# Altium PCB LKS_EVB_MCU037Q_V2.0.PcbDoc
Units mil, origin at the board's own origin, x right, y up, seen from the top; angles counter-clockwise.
Board outline 1880 x 1275 mil, 2 copper layers (Top Layer, Bottom Layer); 38 components, 32 nets, 119 pads, 49 vias.
Unrouted connection lines stored in the file: 3.
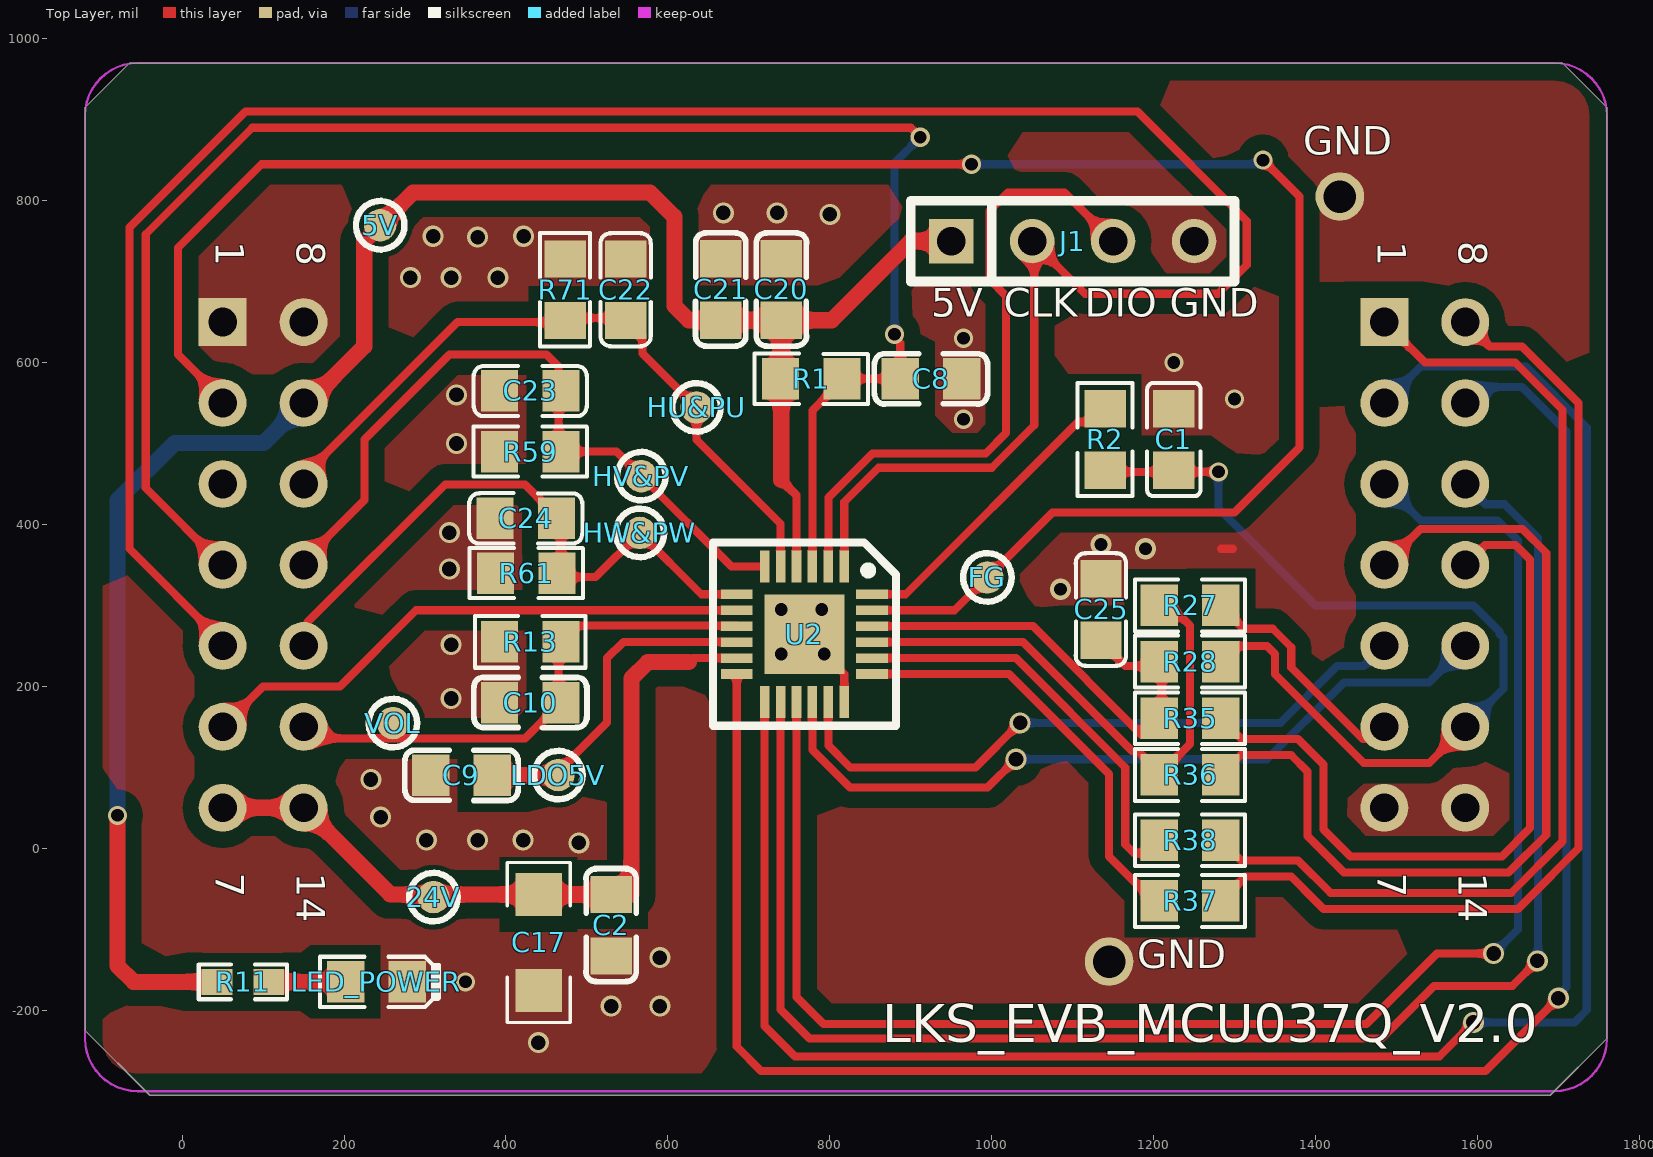
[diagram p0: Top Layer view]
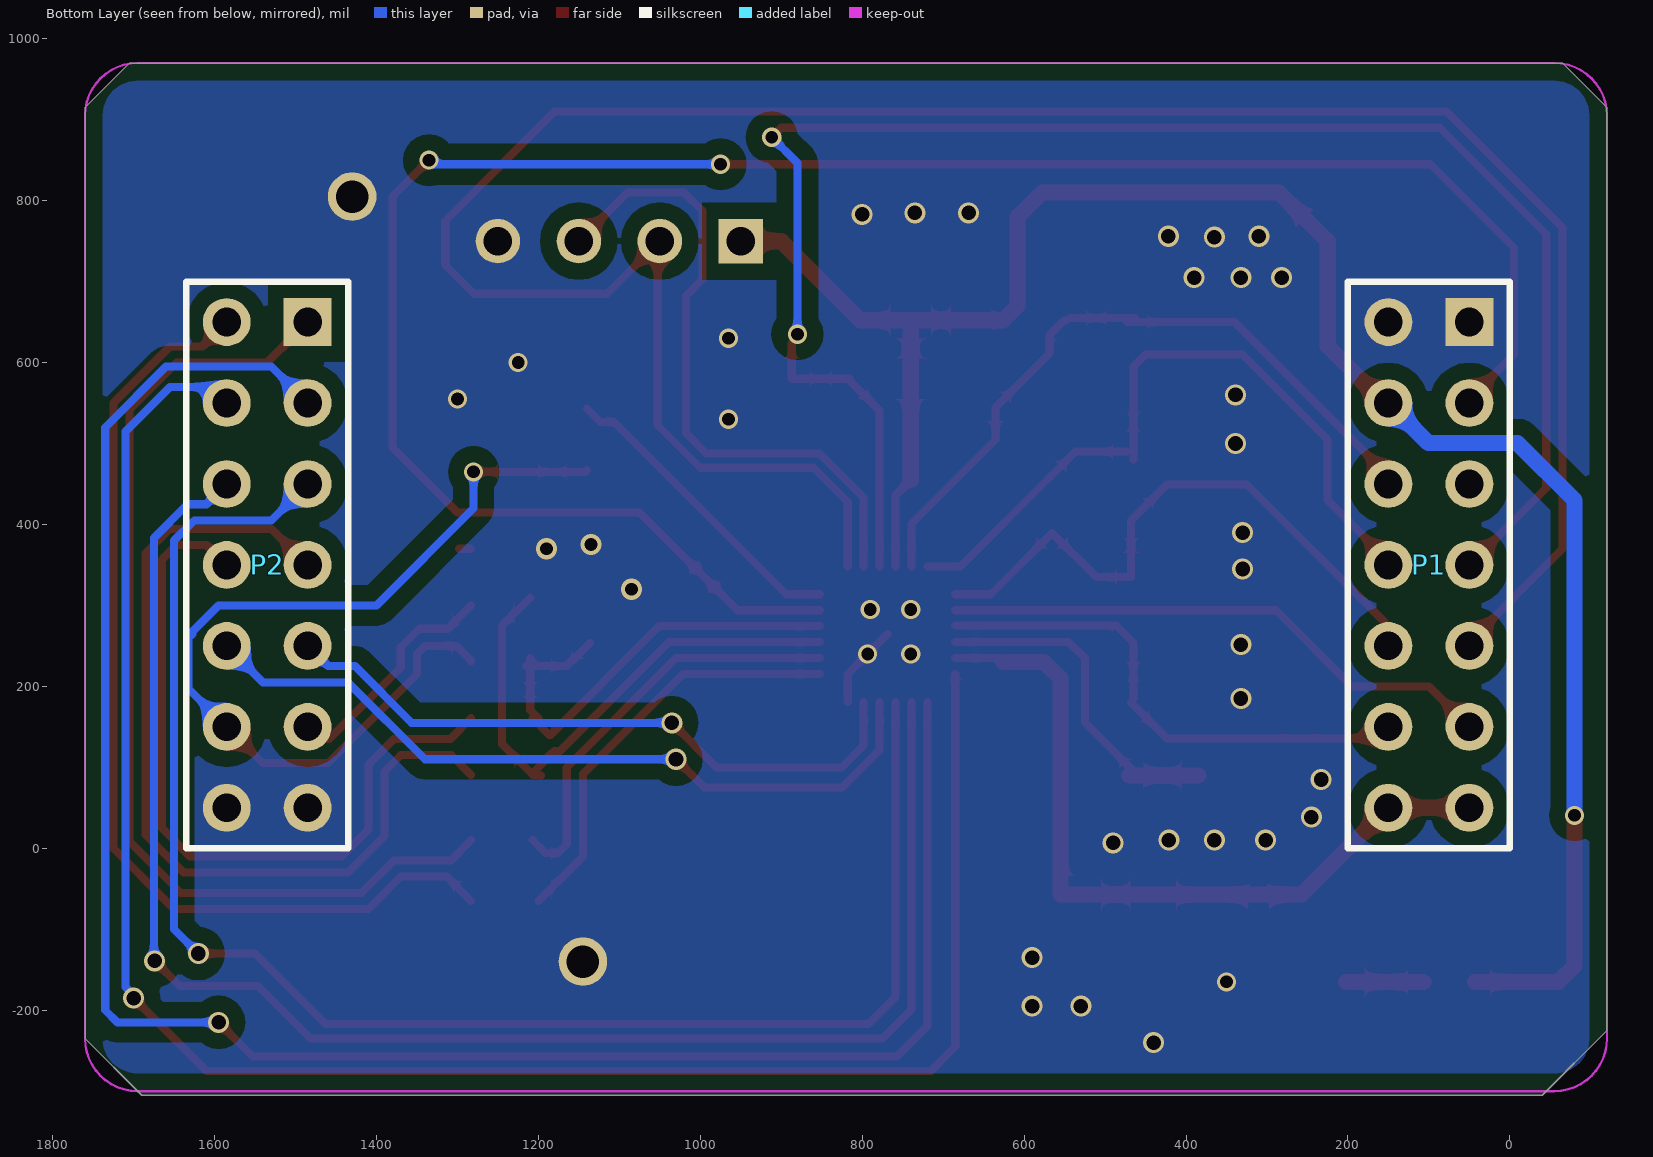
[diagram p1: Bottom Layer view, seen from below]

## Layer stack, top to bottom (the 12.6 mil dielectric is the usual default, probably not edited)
Top Solder: solder mask 0.4, Solder Resist, Dk 3.5
Top Layer: signal copper 1.4
Dielectric1: dielectric 12.6, FR-4, Dk 4.8
Bottom Layer: signal copper 1.4
Bottom Solder: solder mask 0.4, Solder Resist, Dk 3.5

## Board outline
-120,-225 -40,-305 1690,-305 1760,-235 1760,915 1705,970 -65,970 -120,915

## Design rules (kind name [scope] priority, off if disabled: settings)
Clearance Clearance_1 [All vs InPolygon] p1: gap=20 ignorepadtopadclearanceinfootprint=FALSE
Clearance [All] p2: gap=7.87 ignorepadtopadclearanceinfootprint=FALSE
ComponentClearance [All] p1: gap=0 collisioncheckmode=3 verticalgap=0 showdistances=FALSE
FabricationTestpoint [(IsPad And (OnTopLayer Or OnBottomLayer))] p1: side=3 testpointundercomponent=TRUE minsize=40 maxsize=100 preferedsize=60 minholesize=0 maxholesize=40 preferedholesize=32 testpointgrid=1 allowsidetop=TRUE allowsidebottom=TRUE usegrid=TRUE gridtolerance=0.01
PolygonConnect [All] p1: connectstyle=Direct reliefconductorwidth=20 reliefentries=4 polygonreliefangle="90 Angle" airgapwidth=10
RoutingVias [All] p1: holewidth=28 width=50 viastyle="Through Hole" minholewidth=28 minwidth=50 maxholewidth=28 maxwidth=50
SilkToSolderMaskClearance SilkscreenOverComponentPads [IsPad] p1: minsilkscreentomaskgap=10 clearancetoexposedcopper=TRUE
SolderMaskExpansion [All] p1: expansion=4 istentingtop=FALSE
Width [All] p1: maxlimit=300 minlimit=1 preferedwidth=10
27 further rules are at their usual default settings.

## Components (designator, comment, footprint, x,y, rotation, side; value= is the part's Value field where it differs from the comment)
5V "TestP" TP-40 245,770 r0 top
24V "TestP" TP-40 310,-60 r90 top
C1 "1nF/50V" 0805C 1225,505 r270 top
C2 "100nF" 0805C 530,-95 r270 top
C8 "100nF" 0805C 925,580 r0 top
C9 "1uF/10V" 0805C 345,90 r180 top
C10 "100nF" 0805C 430,180 r180 top
C17 "10uF/50V" 1206 440,-175 r90 top
C20 "100nF" 0805C 740.04,690.32 r90 top
C21 "10uF/10V" 0805C 665.04,690.32 r90 top
C22 "1nF/16V" 0805C 548,690 r270 top
C23 "1nF/16V" 0805C 430,565 r0 top
C24 "1nF/16V" 0805C 424.51,407.59 r0 top
C25 "100pF/50V" 0805C 1135,295 r270 top
FG "TestP" TP-40 995,335 r0 top
HU&PU "TestP" TP-40 635,545 r90 top
HV&PV "TestP" TP-40 566.72,460 r90 top
HW&PW "TestP" TP-40 565,390 r90 top
J1 "SWD" SIP4-2.5 1100,750 r0 top
LDO5V "TestP" TP-40 465,90 r270 top
LED_POWER "" 0805D 240,-165 r0 top
P1 "Header 7X2A" HDR2X7_CEN 50,650 r270 bottom
P2 "Header 7X2A" HDR2X7_CEN 1485,650 r270 bottom
R1 "20K" 0805R 777,580 r0 top
R2 "1K" 0805R 1140,505 r90 top
R11 "3.3K" 0603R 75,-165 r180 top
R13 "3.3K" 0805R 430,255 r180 top
R27 "1K" 0805R 1245,300 r0 top
R28 "1K" 0805R 1245,230.59 r0 top
R35 "1K" 0805R 1245,160.59 r180 top
R36 "1K" 0805R 1245,90.59 r180 top
R37 "1K" 0805R 1245,-65 r180 top
R38 "1K" 0805R 1245,10 r180 top
R59 "3.3K" 0805R 430,490 r0 top
R61 "3.3K" 0805R 425,340 r0 top
R71 "3.3K" 0805R 473,690 r270 top
U2 "LKS037Q" QFN24 768.66,264.53 r270 top
VOL "TestP" TP-40 260,155 r90 top

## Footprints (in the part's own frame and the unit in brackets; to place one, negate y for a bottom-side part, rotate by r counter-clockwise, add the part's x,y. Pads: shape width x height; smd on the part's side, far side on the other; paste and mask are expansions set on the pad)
0603R [mil]
  rect 38x32 smd: 1(-32,0) 2(32,0)
  silkscreen extent -54,-22 54,22, body extent -31,-16 32,16, height 18
0805C [mil]
  rect 46x51.18 smd: 1(-38,0) 2(38,0)
  silkscreen extent -70,-33 70,33, body extent -40,-25 38,25, height 22
0805D [mil]
  rect 46x51.18 smd: 1(-38,0) 2(38,0)
  silkscreen extent -70,-31 77,31, body extent -39,-25 39,25, height 22
0805R [mil]
  rect 46x51.18 smd: 1(-38,0) 2(38,0)
  silkscreen extent -70,-31 70,31, body extent -39,-25 39,25, height 22
1206 [mm]
  rect 1.35x1.45 smd: 1(-0.01,-0.01) 2(2.99,-0.01)
  silkscreen extent -1.02,-1 4,0.98
HDR2X7_CEN [mm] "Connector; Header; 7x2 Position"
  rect 1.5x1.5 hole 0.9: 1(0,0)
  round 1.5 hole 0.9: 2(2.54,0) 3(5.08,0) 4(7.62,0) 5(10.16,0) 6(12.7,0) 7(15.24,0) 8(0,-2.54) 9(2.54,-2.54) 10(5.08,-2.54) 11(7.62,-2.54) 12(10.16,-2.54) 13(12.7,-2.54) 14(15.24,-2.54)
  silkscreen extent -1.27,-3.81 16.51,1.27
QFN24 [mm] "4mm*4mm（蒜米工坊）"
  rect 1x0.3 smd: 1(-2.125,1.25) 2(-2.125,0.75) 3(-2.125,0.25) 4(-2.125,-0.25) 5(-2.125,-0.75) 6(-2.125,-1.25) 13(2.125,-1.25) 14(2.125,-0.75) 15(2.125,-0.25) 16(2.125,0.25) 17(2.125,0.75) 18(2.125,1.25)
  rect 0.3x1 smd: 7(-1.25,-2.125) 8(-0.75,-2.125) 9(-0.25,-2.125) 10(0.25,-2.125) 11(0.75,-2.125) 12(1.25,-2.125) 19(1.25,2.125) 20(0.75,2.125) 21(0.25,2.125) 22(-0.25,2.125) 23(-0.75,2.125) 24(-1.25,2.125)
  rect 2.5x2.5 smd: 25(0,0)
  silkscreen extent -2.88,-2.88 2.88,2.88, body extent -2,-2 2,2, height 0.9
SIP4-2.5 [mil]
  rect 55x55 hole 35: 1(-150,0)
  round 55 hole 35: 2(-50,0) 3(50,0) 4(150,0)
  silkscreen extent -200,-50 200,50
TP-40 [mil] "测?"
  round 40 smd: 1(-0.39,-0.39)
  silkscreen extent -30,-30 30,30

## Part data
C1 C8 C9 C20 C21 C22 C23 C24 C25: library part C, "Capacitor"
C2 C10 C17: library part CAP, "Capacitor"
J1: library part "Header 4", "Header, 4-Pin"
LED_POWER: library part LED2, "Typical RED, GREEN, YELLOW, AMBER GaAs LED"
P1 P2: "Header, 7-Pin, Dual row"
R1 R2 R27 R28 R35 R36 R37 R38: library part RES2-1
R11 R13: library part Res2, "Resistor"
R59 R61 R71: library part RES/1
U2: library part LKS32MC037QM6Q8, "CHIP--ldo-QFN"

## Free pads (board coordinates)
  round 60 hole 40: 6(1145,-140) 7(1430,805)

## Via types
v1: diameter 25.98, hole 17.99, Top Layer to Bottom Layer, 31 vias
v2: diameter 23.62, hole 15.75, Top Layer to Bottom Layer, 15 vias
v3: diameter 26, hole 16, Top Layer to Bottom Layer, 3 vias

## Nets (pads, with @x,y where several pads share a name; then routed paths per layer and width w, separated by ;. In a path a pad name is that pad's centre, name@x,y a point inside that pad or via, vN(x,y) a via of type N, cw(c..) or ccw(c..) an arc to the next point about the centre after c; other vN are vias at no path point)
5V: 5V.1 C20.1 C21.1 J1.1 P1.9 R1.1 R11.2 U2.4 | length 2446.7
  Top Layer w10: 740,455 758.82,436.18 U2.4
  Top Layer w20: v2(-80,40.73) -80,-145 -60,-165 R11.2 ; P1.9@155,550 225,620 225,750 5V.1 285,810 578,810 608,780 608,670 625.69,652.32 C21.1 C20.1 802.32,652.32 900,750 J1.1 ; 740,455 740,580 C20.1@740,652
  Bottom Layer w20: v2(-80,40.73) -80,430 -9.53,500.47 100.47,500.47 P1.9
24V_MCU: 24V.1 C2.1 C17.2 P1.7 P1.14 U2.11 | length 956.7
  Top Layer w10: 625.69,230 630.69,235 U2.11
  Top Layer w20: P1.7 P1.14 257,-57 310.39,-57 C2.1 555,-57 555,210 575,230 625.69,230
FG: FG.1 P1.2 U2.23 | length 2586.1
  Top Layer w10: P1.2@55,550 -5,610 -5,741.86 98.14,845 v2(975,845) ; U2.23 954.06,294.06 1075,415 1300,415 1380,495 1380,805 v2(1335,850)
  Bottom Layer w10: v2(975,845) 1326.31,845 1331.31,850 v2(1335,850)
G0: C1.2 P2.13 R2.1 R28.2 | length 1139.2
  Top Layer w10: R2.1 1142,465 v2(1280,465) ; R28.2 1283,232 1301,250 1340,250 1350,240 1350,215 1459.53,105.47 1540.47,105.47 P2.13
  Bottom Layer w10: v2(1280,465) 1280,420 1400,300 1594.96,300 1627.4,267.56 1627.4,264.72 1632.13,260 1632.13,197.13 P2.13
G1: P2.4 R36.1 | length 1117.4
  Top Layer w10: R36.1 1307.41,115 1370,115 1390,95 1390,15 1435,-30 1638.43,-30 1685,16.57 1685,365 1655.47,394.53 1529.53,394.53 P2.4
G2: P2.1 R38.1 | length 1273.4
  Top Layer w10: R38.1 1308,-15 1378.28,-15 1418.28,-55 1641.72,-55 1705,8.28 1705,541.72 1646.72,600 1535,600 P2.1
GND: C1.1 C2.2 C8.2 C9.2 C10.2 C17.1 C20.2 C21.2 C22.1 C23.1 C24.1 C25.1 J1.4 LED_POWER.2 P1.1 P1.8 P2.7 P2.14 pad.6 pad.7 R13.2 R59.1 R61.1 R71.1 U2.18 U2.25 | length 129.1
  Top Layer w10: U2.25 817.87,215.32 U2.18 ; J1.4 J1.4@1256.94,743.06 ; 1283,370 1298.28,370
  other v1: 440,-240 530,-195 590,-195 590,-135 490,6.74 301.58,10 365,10 421.08,10 245.17,38.57 233.18,85 332.17,185 332.24,251.63 330,345 330,390 338.9,500 338.9,560 281.87,705 332.17,705 390,705 365,755 310,756 421.86,756 800,783.04 668.41,785 735,785
  other v2: 350,-165 740,240 793.27,239.92 740,295 790,295 965,530 1300,555 1225,600 965,630
  other v3: 1085,320 1190,370 1135,375
GND0: P2.6 R27.2 | length 291.2
  Top Layer w10: R27.2 1311.82,271.18 1347.1,271.18 1370,248.28 1370,223.28 1458.28,135 1470,135 P2.6
HU&PU: C22.2 HU&PU.1 P1.10 R71.2 U2.5 | length 866.2
  Top Layer w10: P1.10@150,460 340,650 R71.2@473,650 ; R71.2@463,655 C22.2@543,655 ; C22.2 550.59,652 568.59,634 568.59,611.41 HU&PU.1 635.39,504.61 739.13,400.87 U2.5
HV&PV: C23.2 HV&PV.1 P1.11 R59.2 U2.6 | length 898
  Top Layer w10: P1.11@145,350 225,430 225,505 330,610 450,610 465,595 R59.2@465,480 ; R59.2@473,490 536.72,490 HV&PV.1 678.53,348.19 U2.6
HW&PW: C24.2 HW&PW.1 P1.12 R61.2 U2.7 | length 780.3
  Top Layer w10: P1.12@155,242 155,279.41 325,449.41 423.59,449.41 468,405 468,335 510.79,335 HW&PW.1 641.26,313.74 U2.7
LDO5V: C9.1 LDO5V.1 U2.10 | length 424.8
  Top Layer w10: LDO5V.1@460,90.39 525,155.39 525,235 545,255 U2.10@685,255
  Top Layer w20: C9.1@385,90 LDO5V.1@470,90
NetLED_POWER_1: LED_POWER.1 R11.1 | length 95
  Top Layer w20: R11.1 LED_POWER.1
NRST: C8.1 P1.4 R1.2 U2.3 | length 2097.1
  Top Layer w10: P1.4 -45,445 -45,758.43 86.57,890 900,890 v2(911.7,878.3) ; U2.3 778.5,540.91 815,577.41 R1.2 C8.1 887,624.31 880,631.31 v2(880,635)
  Bottom Layer w10: v2(880,635) 880,846.6 v2(911.7,878.3)
OC: R2.2 U2.24 | length 382.6
  Top Layer w10: U2.24 893.74,313.74 1106.6,526.6 1123.6,526.6 R2.2
OPA2_IN: R38.2 U2.20 | length 516.9
  Top Layer w10: U2.20 1030,235 1165,100 1165,4.61 1175.46,-5.86 1191.14,-5.86 R38.2
OPA2_IP: R37.2 U2.19 | length 523.4
  Top Layer w10: U2.19 1021.4,215.32 1145,91.72 1145,-10 R37.2@1200,-65
OPA3_IN: R27.1 R36.2 U2.21 | length 683.9
  Top Layer w10: U2.21 1038.6,254.69 1173.28,120 1180.18,120 1207,93.18 R36.2 R36.2@1196.72,90 ; R36.2@1207,90.79 1245,128.79 1245,275 R27.1@1210,310
OPA3_IP: C25.2 R28.1 R35.2 U2.22 | length 597.4
  Top Layer w10: U2.22 1050.91,274.37 1185.14,140.14 1186.55,140.14 R35.2 ; C25.2@1136.45,253.55 1165,225 R28.1@1210,225 ; R35.2@1200,160.59 1210,170.59 R28.1@1210,225 ; R28.1 1215,225 R28.1@1210,225 ; R28.1@1210,235 R28.1@1210,225
RXD: P1.6 U2.8 | length 694.7
  Top Layer w10: P1.6 100,200 195,200 289.05,294.05 U2.8
SPin: P1.3
SWCLK: J1.2 P1.5 U2.1 | length 2994.4
  Top Layer w10: P1.5@50,255 -65,370 -65,766.72 78.28,910 1180,910 1315,775 1315,720.28 1279.72,685 1115,685 J1.2@1052.5,747.5 ; U2.1 817.87,427.87 860,470 1000,470 1052.5,522.5 J1.2@1052.5,747.5 ; J1.2 J1.2@1052.5,747.5
SWDIO: J1.3 U2.2 | length 807.3
  Top Layer w10: U2.2 798.19,433.47 852.6,487.87 992.6,487.87 1017.7,512.97 1017.7,682.3 997.5,702.5 997.5,787.5 1020,810 1090,810 J1.3
UH: P2.9 U2.12 | length 2385.2
  Top Layer w10: U2.12 685,-245 715,-275 1610,-275 v1(1700,-185)
  Bottom Layer w10: P2.9 1605,570 1655,570 1710,515 1710,-171.15 1700,-181.15 v1(1700,-185)
UL: P2.2 U2.13 | length 2474.8
  Top Layer w10: U2.13 719.45,-219.45 757.13,-257.13 1552.87,-257.13 v1(1595,-215)
  Bottom Layer w10: P2.2 1530,595 1660,595 1735,520 1735,-200 1720,-215 v1(1595,-215)
UX: P2.8 R37.1 | length 1233.5
  Top Layer w10: R37.1 1313,-35 1370,-35 1400,-65 1410,-75 1650,-75 1660,-65 1725,0 1725,550 1655,620 1615,620 P2.8
VH: P2.10 U2.14 | length 2009.9
  Top Layer w10: U2.14 739.13,-199.13 775,-235 1481.46,-235 1524.13,-192.33 ; 1524.13,-192.28 1546.41,-170 1643.06,-170 v1(1674.03,-139.03)
  Bottom Layer w10: P2.10 1610,425 1633.28,425 1675,383.28 1675,-138.06 v1(1674.03,-139.03)
VL: P2.3 U2.15 | length 1992.2
  Top Layer w10: U2.15 758.82,-183.82 792.13,-217.13 1462.87,-217.13 1550,-130 v1(1620,-130)
  Bottom Layer w10: P2.3 1530,405 1625,405 1650,380 1650,-100 v1(1620,-130)
VOL: C10.1 P1.13 R13.1 U2.9 VOL.1 | length 642.1
  Top Layer w10: P1.13@150,155 169.41,135.59 423.59,135.59 C10.1 ; C10.1@465,185 465,253.9 486,274.9 497.9,274.9 498,275 U2.9@685,275
VX: P2.11 R35.1 | length 943.4
  Top Layer w10: R35.1 1308.59,135 1378.28,135 1410,103.28 1410,23.28 1443.28,-10 1630.15,-10 1665,24.85 1665,356.72 1647.19,374.53 1609.53,374.53 P2.11
WH: P2.12 U2.16 | length 961.9
  Top Layer w10: U2.16 778.5,121.5 825,75 995,75 v1(1030,110) v1@1026.94,113.06
  Bottom Layer w10: v1(1030,110) 1340,110 1435,205 1540,205 P2.12
WL: P2.5 U2.17 | length 817.5
  Top Layer w10: U2.17 798.19,127.09 825.28,100 980,100 v1(1035,155) v1@1032.49,157.51
  Bottom Layer w10: v1(1035,155) 1356.72,155 1426.72,225 1460,225 P2.5

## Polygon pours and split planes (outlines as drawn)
GND on Top Layer "Bottom Layer-No Net" (solid, remove dead copper, pour order 3): -125,970 -125,-300 1750,-300 1755,-295 1755,970
GND on Bottom Layer "Bottom Layer-No Net" (solid, remove dead copper, pour order 4): -120,970 -120,-300 1755,-300 1760,-295 1760,970

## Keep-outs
Keep-Out Layer:
  lines w2.99: -120,-235 ccw(c-55,-235) -55,-300 ; -120,905 cw(c-55,905) -55,970 ; 1695,-300 ccw(c1695,-235) 1760,-235 ; 1695,970 cw(c1695,905) 1760,905
  lines w3: -120,-235 -120,905 ; -55,-300 1695,-300 ; -55,970 1695,970 ; 1760,-235 1760,905

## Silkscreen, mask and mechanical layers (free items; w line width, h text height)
Top Overlay:
  text "GND" at 1385,845 h60
  text "5V" at 925,645 h60
  text "CLK" at 1015,645 h60
  text "DIO" at 1115,645 h60
  text "GND" at 1220,645 h60
  text "GND" at 1180,-160 h60
  text "LKS_EVB_MCU037Q_V2.0" at 865,-255 h80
